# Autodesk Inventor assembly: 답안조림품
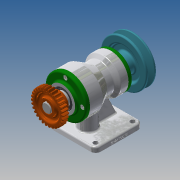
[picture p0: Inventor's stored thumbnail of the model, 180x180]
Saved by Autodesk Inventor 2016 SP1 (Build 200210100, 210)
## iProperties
Created: 2019-01
Part Number: 답안조림품
Document SubType Name: Assembly
Designer: Administrator
Author: Administrator
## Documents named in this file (15)
- \\d4\D4\ATC마스터자격증시험\490107V1052 김진희\490107V1052\답안조림품.iam
- \\d4\D4\ATC마스터자격증시험\490107V1052 김진희\490107V1052\본체.ipt
- \\d4\D4\ATC마스터자격증시험\490107V1052 김진희\490107V1052\베어링 6203.ipt
- \\d4\D4\ATC마스터자격증시험\490107V1052 김진희\490107V1052\베어링 6205.ipt
- \\d4\D4\ATC마스터자격증시험\490107V1052 김진희\490107V1052\축.ipt
- \\d4\D4\ATC마스터자격증시험\490107V1052 김진희\490107V1052\앞커버.ipt
- \\d4\D4\ATC마스터자격증시험\490107V1052 김진희\490107V1052\뒤커버.ipt
- \\d4\D4\ATC마스터자격증시험\490107V1052 김진희\490107V1052\오일 실 25 38 8.ipt
- \\d4\D4\ATC마스터자격증시험\490107V1052 김진희\490107V1052\오일 실 17 30 8.ipt
- \\d4\D4\ATC마스터자격증시험\490107V1052 김진희\490107V1052\볼트 M4.ipt
- \\d4\D4\ATC마스터자격증시험\490107V1052 김진희\490107V1052\키 6 x 6 x 18.ipt
- \\d4\D4\ATC마스터자격증시험\490107V1052 김진희\490107V1052\키 5 x 5 x 20.ipt
- \\d4\D4\ATC마스터자격증시험\490107V1052 김진희\490107V1052\스퍼기어.ipt
- \\d4\D4\ATC마스터자격증시험\490107V1052 김진희\490107V1052\V-벨트풀리.ipt
- \\d4\D4\ATC마스터자격증시험\490107V1052 김진희\490107V1052\멈춤나사 M3.ipt
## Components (1 placed, 1 different names)
1. V-벨트풀리:1 — 각도:2
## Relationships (1: Angle 1)
- 각도:2 [Angle]: V-벨트풀리:1
